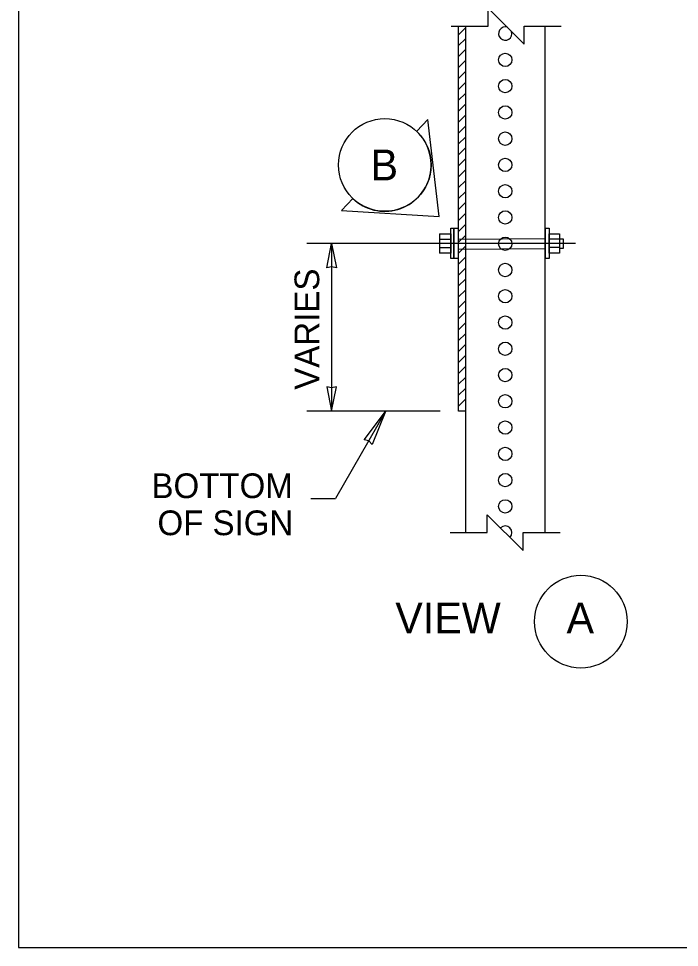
# Model space of a CAD drawing. Extents: x 99862 to 103680, y 99470 to 102076.
# Drawn here: x 99862 to 100290, y 100000 to 100601 of the extents above; entities that cross this region are included whole.
import ezdxf

# ---------------------------------------------------------------- set-up
doc = ezdxf.new("R2010")
doc.units = 0
for name, color, linetype in [('Level 1', 7, 'Continuous'), ('Level 15', 7, 'Continuous'), ('Level 2', 7, 'Continuous'), ('Level 20', 7, 'Continuous'), ('Level 3', 7, 'Continuous'), ('Level 60', 7, 'Continuous')]:
    doc.layers.add(name, color=color, linetype=linetype)

msp = doc.modelspace()

# ---------------------------------------------------------------- linework, layer by layer
at = {"layer": 'Level 1'}
for p, q in [((100147, 100590.25), (100151.46, 100594.71)), ((100147, 100583.18), (100151.46, 100587.64)), ((100147, 100576.11), (100151.46, 100580.57)), ((100147, 100569.04), (100151.46, 100573.5)), ((100147, 100561.96), (100151.46, 100566.42)), ((100147, 100554.89), (100151.46, 100559.35)), ((100147, 100547.82), (100151.46, 100552.28)), ((100147, 100540.75), (100151.46, 100545.21)), ((100147, 100533.68), (100151.46, 100538.14)), ((100147, 100526.61), (100151.46, 100531.07)), ((100147, 100519.54), (100151.46, 100524)), ((100147, 100512.47), (100151.46, 100516.93)), ((100147, 100505.4), (100151.46, 100509.86)), ((100147, 100498.33), (100151.46, 100502.78)), ((100147, 100491.25), (100151.46, 100495.71)), ((100147, 100484.18), (100151.46, 100488.64)), ((100147, 100477.11), (100151.46, 100481.57)), ((100147, 100470.04), (100151.46, 100474.5)), ((100147, 100462.97), (100151.46, 100467.43)), ((100147, 100455.9), (100151.46, 100460.36)), ((100147, 100448.83), (100151.46, 100453.29)), ((100203.15, 100456.57), (100203.15, 100457.58)), ((100203.15, 100453.89), (100203.15, 100454.9)), ((100203.15, 100451.88), (100203.15, 100452.21)), ((100147, 100441.76), (100151.46, 100446.22)), ((100147, 100434.69), (100151.46, 100439.15)), ((100147, 100427.61), (100151.46, 100432.07)), ((100147, 100420.54), (100151.46, 100425)), ((100147, 100413.47), (100151.46, 100417.93)), ((100147, 100406.4), (100151.46, 100410.86)), ((100147, 100399.33), (100151.46, 100403.79)), ((100147, 100392.26), (100151.46, 100396.72)), ((100147, 100385.19), (100151.46, 100389.65)), ((100147, 100378.12), (100151.46, 100382.58)), ((100147, 100371.05), (100151.46, 100375.51)), ((100147, 100363.97), (100151.46, 100368.43)), ((100147, 100356.9), (100151.46, 100361.36)), ((100147, 100349.83), (100151.46, 100354.29))]:
    msp.add_line(p, q, dxfattribs=at)
msp.add_lwpolyline([(99862, 99999.5), (103151, 99999.5), (103151, 102075.5), (99862, 102075.5)], close=True, dxfattribs=at)
msp.add_lwpolyline([(100151.46, 100595.8), (100151.46, 100346.62), (100147, 100346.62), (100147, 100595.8)], dxfattribs=at)
at = {"layer": 'Level 15'}
for p, q in [((100135, 100346.62), (100048.7, 100346.62)), ((100099.73, 100346.35), (100067.23, 100290.06)), ((100051.23, 100290.06), (100067.23, 100290.06))]:
    msp.add_line(p, q, dxfattribs=at)
for points in [[(100142.21, 100595.8), (100166.21, 100595.8), (100166.21, 100607.42), (100189.44, 100584.19), (100189.44, 100595.8), (100213.44, 100595.8)], [(100064.7, 100455.06), (100064.7, 100346.62)], [(100141.57, 100267.96), (100165.57, 100267.96), (100165.57, 100279.58), (100188.8, 100256.35), (100188.8, 100267.96), (100212.8, 100267.96)]]:
    msp.add_lwpolyline(points, dxfattribs=at)
for points in [[(100064.7, 100455.06), (100067.79, 100439.34), (100064.7, 100440.07), (100061.62, 100439.34)], [(100064.7, 100346.62), (100067.79, 100362.35), (100064.7, 100361.62), (100061.62, 100362.35)], [(100099.73, 100346.35), (100090.9, 100325.09), (100088.84, 100327.49), (100085.73, 100328.07)]]:
    msp.add_lwpolyline(points, close=True, dxfattribs=at)
at = {"layer": 'Level 2'}
for points in [[(100202.92, 100267.96), (100202.92, 100595.8)], [(100151.46, 100346.62), (100151.46, 100267.96)]]:
    msp.add_lwpolyline(points, dxfattribs=at)
for centre in [(100177.19, 100573.96), (100177.19, 100556.96), (100177.19, 100539.96), (100177.19, 100522.96), (100177.19, 100505.96), (100177.19, 100488.96), (100177.19, 100471.96), (100177.19, 100454.96), (100177.19, 100437.96), (100177.19, 100420.96), (100177.19, 100403.96), (100177.19, 100386.96), (100177.19, 100369.96), (100177.19, 100352.96), (100177.19, 100335.96), (100177.19, 100318.96), (100177.19, 100301.96), (100177.19, 100284.96)]:
    msp.add_circle(centre, 4.32, dxfattribs=at)
for centre, start, end in [((100177.19, 100590.96), 71.32698, 18.67302), ((100177.19, 100267.96), 315, 135)]:
    msp.add_arc(centre, 4.32, start, end, dxfattribs=at)
at = {"layer": 'Level 20'}
for p, q in [((100127.13, 100535.39), (100119.83, 100527.71)), ((100134.31, 100472.58), (100127.13, 100535.39)), ((100078.51, 100484.2), (100071.21, 100476.52)), ((100071.21, 100476.52), (100134.31, 100472.58)), ((100222.77, 100455.06), (100048.7, 100455.06))]:
    msp.add_line(p, q, dxfattribs=at)
for centre in [(100099.17, 100505.95), (100226.09, 100210.35)]:
    msp.add_circle(centre, 30, dxfattribs=at)
msp.add_arc((100099.17, 100505.95), 30, 226.47389, 46.47832, dxfattribs=at)
at = {"layer": 'Level 3'}
for p, q in [((100134.7, 100461.27), (100134.7, 100448.86)), ((100212.41, 100461.27), (100212.41, 100448.86)), ((100203.15, 100458.07), (100147.13, 100457.67)), ((100203.15, 100451.7), (100147.13, 100451.3))]:
    msp.add_line(p, q, dxfattribs=at)
for points in [[(100141.91, 100465.11), (100143.97, 100465.11), (100143.97, 100445.35), (100141.91, 100445.35)], [(100143.97, 100465.11), (100146.71, 100465.11), (100146.71, 100445.35), (100143.97, 100445.35)], [(100203.15, 100465.11), (100205.55, 100465.11), (100205.55, 100445.35), (100203.15, 100445.35)]]:
    msp.add_lwpolyline(points, close=True, dxfattribs=at)
for points in [[(100134.7, 100461.27), (100141.91, 100461.27), (100141.91, 100448.86), (100134.7, 100448.86)], [(100212.41, 100448.86), (100205.55, 100448.86), (100205.55, 100461.27), (100212.41, 100461.27)], [(100134.7, 100457.91), (100141.91, 100457.91)], [(100212.41, 100457.91), (100205.55, 100457.91)], [(100212.41, 100458.15), (100214.77, 100458.15), (100214.77, 100451.78), (100212.41, 100451.78)], [(100134.7, 100452.55), (100141.91, 100452.55)], [(100212.41, 100452.55), (100205.55, 100452.55)]]:
    msp.add_lwpolyline(points, dxfattribs=at)
at = {"layer": 'Level 60'}
msp.add_line((99862, 99999.5), (99862, 99999.5), dxfattribs=at)

# ---------------------------------------------------------------- texts
at = {"layer": 'Level 20'}
for s, height, p in [('B', 20, (100089.93, 100495.95)), ('BOTTOM', 16, (99948.08, 100290.32)), ('OF SIGN', 16, (99951.95, 100266.32)), ('VIEW', 20, (100105.94, 100202.73)), ('A', 20, (100216.85, 100202.73))]:
    msp.add_text(s, height=height, dxfattribs=at).set_placement(p)
msp.add_text('VARIES', height=16, rotation=90, dxfattribs=at).set_placement((100056.7, 100360.42))

doc.saveas('drawing.dxf')
